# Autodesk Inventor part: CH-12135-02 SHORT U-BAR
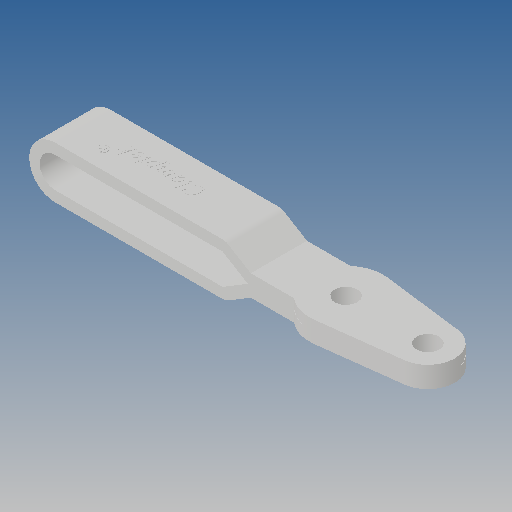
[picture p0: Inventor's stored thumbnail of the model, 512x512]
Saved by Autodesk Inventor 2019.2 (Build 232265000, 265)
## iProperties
Created: 2012-09
Part Number: CH-12135-02 SHORT U-BAR
Material: Ogólny
Document SubType Name: Modeling
Designer: CADENGINEERING4
Density: 1 g/cm^3
Appearance: Domyślna
Author: CADENGINEERING4
Revision Number: ÈÎºÎ
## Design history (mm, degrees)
feature "ÇÐ³ý-À­Éì2"
feature "ÇÐ³ý-À­Éì6"
node "Bryła1"
node "Bryła2"
